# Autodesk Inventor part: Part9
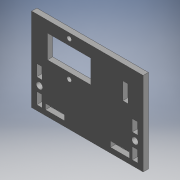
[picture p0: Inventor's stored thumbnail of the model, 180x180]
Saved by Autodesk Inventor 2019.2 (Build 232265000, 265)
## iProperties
Part Number: Part9
Material: Generic
Document SubType Name: Modeling
Designer: richard.girt
Mass: 6.06285 g
Surface Area: 56.1407 cm^2
Volume: 6.06285 cm^3
Density: 1 g/cm^3
Appearance: Default
Author: richard.girt
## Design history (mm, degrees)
sketch "Sketch1"
  geometry: L1 (-30, 0)-(30, 0); L2 (30, 0)-(30, 45); L3 (30, 45)-(-30, 45); L4 (-30, 45)-(-30, 0); L5 (-21.5, 39)-(1.9, 39); L6 (1.9, 39)-(1.9, 26.5); L7 (1.9, 26.5)-(-21.5, 26.5); L8 (-21.5, 26.5)-(-21.5, 39); L9 (-22.6, 5.7)-(-12.4, 5.7); L10 (-12.4, 5.7)-(-12.4, 2.7); L11 (-12.4, 2.7)-(-22.6, 2.7); L12 (-22.6, 2.7)-(-22.6, 5.7); L13 (19, 37)-(22, 37); L14 (22, 37)-(22, 27.75); L15 (22, 27.75)-(19, 27.75); L16 (19, 27.75)-(19, 37); L17 (12.4, 5.7)-(22.6, 5.7); L18 (22.6, 5.7)-(22.6, 2.7); L19 (22.6, 2.7)-(12.4, 2.7); L20 (12.4, 2.7)-(12.4, 5.7); L21 (12.4, 4.2)-(-12.4, 4.2); 3 further points
  constraints: 42 end point, 10 parallel, 6 perpendicular, 5 horizontal, 4 midpoint, 2 collinear, 1 coincident, 1 vertical alignment
  dimensions: "d0" = 60 distance of L1.start L1.end; "d1" = 45 distance of L3.end L1.start; "d2" = 23.4 distance of L5.start L5.end; "d3" = 12.5 distance of L5.end L6.end; "d4" = 8.5 distance between parallel lines of L4 L8; "d6" = 3 distance of L13.start L13.end; "d8" = 8 distance between parallel lines of L2 L14; "d9" = 9.25 distance of L13.end L14.end; "d10" = 10.2 distance of L10.end L11.end; "d11" = 10.2 distance of L18.end L19.end; "d14" = 2.7 distance between parallel lines of L19 L1; "d33" = 24.8 distance of L21.start L21.end; "d46" = 27.75 distance between parallel lines of L15 L1; "d47" = 26.5 distance between parallel lines of L7 L1
extrude "Extrusion1" new body sketch "Sketch1" distance "d15" = 2.8; taper "d16" = 0 deg
sketch "Sketch2"
  geometry: L1 (30, 0)-(30, 45) reference; L2 (-30, 45)-(-30, 0) reference; L3 (-27.3, 21.9)-(-24.3, 21.9); L4 (-24.3, 21.9)-(-24.3, 15.7); L5 (-24.3, 15.7)-(-27.3, 15.7); L6 (-27.3, 15.7)-(-27.3, 21.9); L7 (-27.3, 8.9)-(-24.3, 8.9); L8 (-24.3, 8.9)-(-24.3, 2.7); L9 (-24.3, 2.7)-(-27.3, 2.7); L10 (-27.3, 2.7)-(-27.3, 8.9); L11 (24.3, 2.7)-(27.3, 2.7); L12 (27.3, 2.7)-(27.3, 8.9); L13 (27.3, 8.9)-(24.3, 8.9); L14 (24.3, 8.9)-(24.3, 2.7); L15 (24.3, 15.7)-(27.3, 15.7); L16 (27.3, 15.7)-(27.3, 21.9); L17 (27.3, 21.9)-(24.3, 21.9); L18 (24.3, 21.9)-(24.3, 15.7); L19 (-30, 0)-(30, 0) reference; L20 (-25.8, 15.7)-(-25.8, 8.9); 2 further points
  constraints: 34 end point, 8 parallel, 5 equal length, 4 horizontal, 4 perpendicular, 4 point on line, 3 midpoint, 1 collinear
  dimensions: "d17" = 6.2 distance of L9.end L7.start; "d19" = 2.7 distance between parallel lines of L2 L10; "d20" = 2.7 distance between parallel lines of L12 L1; "d34" = 3 distance of L11.start L11.end (derived); "d43" = 12.3 distance from line of point (-25.8, 12.3) L19; "d44" = 3 distance of L8.end L9.end; "d45" = 19.2 distance between parallel lines of L3 L9
extrude "Extrusion2" cut sketch "Sketch2" distance "d21" = 2.8; taper "d22" = 0 deg
sketch "Sketch3"
  geometry: L1 (24.3, 8.9)-(27.3, 8.9) reference; L2 (-24.3, 15.7)-(-27.3, 15.7) reference; L3 (-27.3, 8.9)-(-24.3, 8.9) reference; L4 (27.3, 15.7)-(24.3, 15.7) reference; L5 (1.9, 39)-(1.9, 26.5) reference; L6 (-21.5, 39)-(1.9, 39) reference; L7 (-9.8, 42.25)-(-9.8, 32.75); L8 (-9.8, 32.75)-(-9.8, 23.25); L9 (-25.8, 15.7)-(-25.8, 8.9); L10 (25.8, 15.7)-(25.8, 8.9); 7 further points
  constraints: 8 end point, 8 midpoint, 2 coincident, 2 point on line, 1 collinear, 1 horizontal alignment, 1 vertical
  dimensions: "d23" = 19 distance of L8.end L7.start
hole "Hole1" sketch "Sketch3" at (-25.8, 12.3), (25.8, 12.3), (-9.8, 23.25), (-9.8, 42.25) diameter "d24" = 2.5; stored, may be unused: countersink angle "d28" = 90 deg, drill point angle "d30" = 118 deg; dims "d25" = 6, "d26" = 4, "d27" = 2, "d29" = 8
sketch "Sketch4"
  geometry: C1 r 1.25 at (-25.8, 12.3) reference; C2 r 1.25 at (25.8, 12.3) reference; 3 further points
  constraints: 2 coincident
hole "Hole2" sketch "Sketch4" at (-25.8, 12.3), (25.8, 12.3) diameter "d36" = 3.5; stored, may be unused: countersink angle "d40" = 90 deg, drill point angle "d42" = 118 deg; dims "d37" = 6, "d38" = 4, "d39" = 2, "d41" = 8
fillet "Fillet1" dims "d31" = 4
fillet "Fillet2" dims "d32" = 10
body "Solid1"
